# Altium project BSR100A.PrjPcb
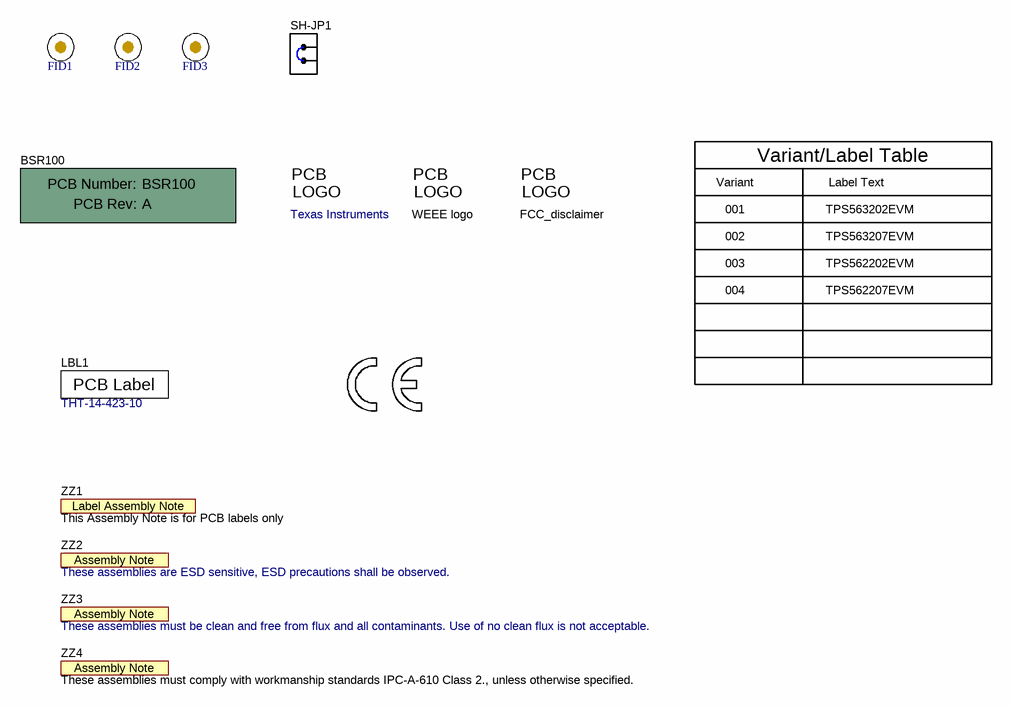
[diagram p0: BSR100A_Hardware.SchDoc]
CopyrightYear: 2019; PCB_Layout: Zhao Ma; PCB_Rev: A; PRJ_Customer: Public Release; PRJ_Engineer: Zhao Ma; PRJ_Number: BSR100; PRJ_Title: BSR100; SCH_Rev: A; TechSupport: http://www.ti.com/support; TID: A0223841
2 sheets, 47 parts. Net scope: global (net labels, ports and power ports of the same name join across sheets).
Board file: BSR100A.PcbDoc
Sheets:
  BSR100A_Hardware.SchDoc
  BSR100A.SchDoc

## Sheet BSR100A_Hardware.SchDoc
size 431 x 279 mm; Date: Not shown in title block; ApprovedBy: Not shown in title block; CheckedBy: Not shown in title block; Author: Not shown in title block; CompanyName: Not shown in title block; Engineer: Not shown in title block; Organization: Not shown in title block; Address1: Not shown in title block; Address2: Not shown in title block; Address3: Not shown in title block; Address4: Not shown in title block; DocumentNumber: 1; Revision: Use project parameter SCH_Rev; SheetNumber: 1; SheetTotal: 2; PageSetup: Record=PageOptions¦CenterHorizontal=True¦CenterVertical=True¦PrintScale=1.00¦XCorrection=1.00¦YCorrection=1.00¦PrintKind=0¦BorderSize=5000000¦LeftOffset=0¦BottomOffset=0¦Orientation=2¦PaperLength=1000¦PaperWidth=1000¦Scale=100¦PaperSource=15¦PrintQuality=600¦MediaType=1¦DitherType=10¦PaperKind=Letter¦PrintScaleMode=1

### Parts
!PCB1  PartNumber: BSR100  (hidden comment: Printed Circuit Board)  (mechanical)
FID1  Fiducial  [Fiducial10-20]  (value not drawn)
FID2  Fiducial  [Fiducial10-20]  (value not drawn)
FID3  Fiducial  [Fiducial10-20]  (value not drawn)
LBL1  THT-14-423-10  [Label_650x200]
Logo1  Texas Instruments  [TI_Stacked_Overlay_Small]  (no BOM)
Logo2  WEEE logo  [WEEE_Minimum]  (no BOM)
Logo3  FCC disclaimer  [FCC_disclaimer]  (value not drawn)  (no BOM)
LOGO4  CE Mark  [CE_Mark_5mm]  (value not drawn)  (no BOM)
SH-JP1  SNT-100-BK-G  [SNT-100-BK-G]  (value not drawn)
ZZ1  This Assembly Note is for PCB labels only  [AssemblyNoteLabel]  (no BOM)
ZZ2  These assemblies are ESD sensitive, ESD precautions shall be observed.  [AssemblyNote]  (no BOM)
ZZ3  These assemblies must be clean and free from flux and all contaminants. Use of no clean flux is not acceptable.  [AssemblyNote]  (no BOM)
ZZ4  These assemblies must comply with workmanship standards IPC-A-610 Class 2., unless otherwise specified.  [AssemblyNote]  (no BOM)

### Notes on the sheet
- Variant
- 001
- Variant/Label Table
- Label Text
- TPS563202EVM
- 002
- 003
- TPS563207EVM
- TPS562202EVM
- 004
- TPS562207EVM

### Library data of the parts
!PCB1 = CMP-0003618-2: Manufacturer: Any
FID1-FID3 = CMP-0077181-1: Fiducial mark.  There is nothing to buy or mount.
LBL1 = CMP-0003625-1: Thermal Transfer Printable Labels, 0.650" W x 0.200" H - 10,000 per roll; Manufacturer: Brady; Note: Size: 0.65" x 0.20 "
Logo1 = CMP-0074838-1: Texas Instrument Corporate Signature; SymbolCreator: a0412235; Lib Reference: TI_Logo
Logo2 = CMP-0074769-1
Logo3 = CMP-0074847-1: FCC_disclaimer; Library Reference: Logo
LOGO4 = CMP-0074844-1: SymbolCreator: a0412235
SH-JP1 = CMP-0003623-3: Shunt, 100mil, Gold plated, Black; Alternate PartNumber: 969102-0000-DA; Manufacturer: Samtec; Alternate Manufacturer: 3M; Value: 1x2; Note: You can "mate" this to a header by matching the designator.  i.e. use SH-J3 for header J3
ZZ1 = CMP-0003616-3
ZZ2 = CMP-0077236-1
ZZ3 = CMP-0077237-1
ZZ4 = AssemblyNote: SymbolCreator: codlsc

## Sheet BSR100A.SchDoc
size 431 x 279 mm; Date: Not shown in title block; ApprovedBy: Not shown in title block; CheckedBy: Not shown in title block; Author: Not shown in title block; CompanyName: Not shown in title block; Engineer: Not shown in title block; Organization: Not shown in title block; Address1: Not shown in title block; Address2: Not shown in title block; Address3: Not shown in title block; Address4: Not shown in title block; DocumentNumber: 1; Revision: Use project parameter SCH_Rev; SheetNumber: 2; SheetTotal: 3; PageSetup: Record=PageOptions¦CenterHorizontal=True¦CenterVertical=True¦PrintScale=1.00¦XCorrection=1.00¦YCorrection=1.00¦PrintKind=0¦BorderSize=5000000¦LeftOffset=0¦BottomOffset=0¦Orientation=2¦PaperLength=1000¦PaperWidth=1000¦Scale=100¦PaperSource=15¦PrintQuality=600¦MediaType=1¦DitherType=10¦PaperKind=Letter¦PrintScaleMode=1
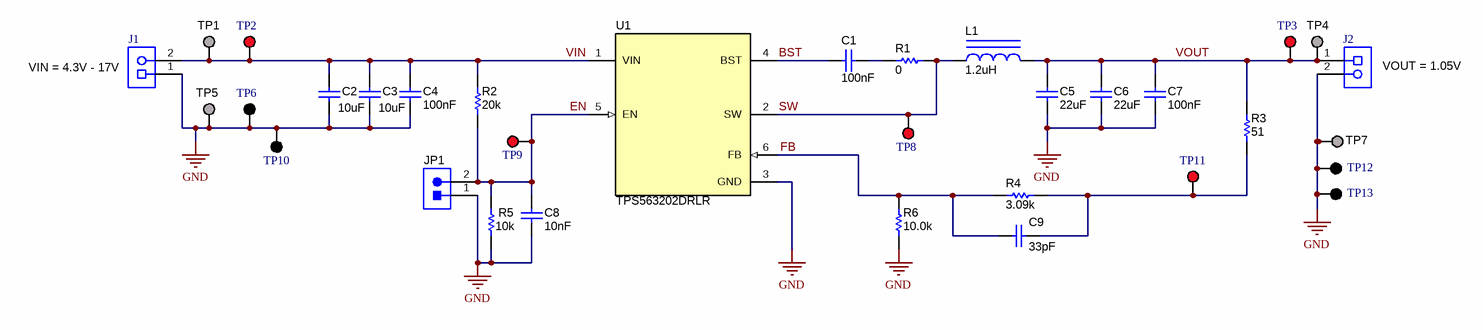
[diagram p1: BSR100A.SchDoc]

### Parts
C1  Cap_F: 100nF  [0603]  (hidden comment: C1608X7R1E104K080AA)
C2  ValueDisplayed: 10uF  [0805_HV]  (hidden comment: GRM21BR61E106MA73L)
C3  ValueDisplayed: 10uF  [0805_HV]  (hidden comment: GRM21BR61E106MA73L)
C4  Cap_F: 100nF  [0603]  (hidden comment: C1608X7R1E104K080AA)
C5  ValueDisplayed: 22uF  [0805_HV]  (hidden comment: GRM21BR61A226ME44L)
C6  ValueDisplayed: 22uF  [0805_HV]  (hidden comment: GRM21BR61A226ME44L)
C7  Cap_F: 100nF  [0603]  (hidden comment: C1608X7R1E104K080AA)
C8  Cap_F: 10nF  [0603]  (hidden comment: C1608X7R1H103K080AA)
C9  ValueDisplayed: 33pF  [0603]  (hidden comment: GRM1885C2A330JA01D)
J1  ED120/2DS  [On-Shore_ED120_2DS]  (value not drawn)
J2  ED120/2DS  [On-Shore_ED120_2DS]  (value not drawn)
JP1  PEC02SAAN  [CONN_PEC02SAAN]  (value not drawn)
L1  ValueDisplayed: 1.2uH  [WE-LHMI_7050]  (hidden comment: 74437349012)
R1  ValueDisplayed: 0  [0603]  (hidden comment: CRCW06030000Z0EA)
R2  ValueDisplayed: 20k  [0603]  (hidden comment: CRCW060320K0JNEA)
R3  ValueDisplayed: 51  [0603]  (hidden comment: CRCW060351R0JNEA)
R4  ValueDisplayed: 3.09k  [0603]  (hidden comment: RC0603FR-073K09L)
R5  ValueDisplayed: 10k  [0603]  (hidden comment: CRCW060310K0JNEA)
R6  value 10.0k  [0603]  (hidden comment: CRCW060310K0FKEA)
TP1  1502-2  [Keystone1502-2]  (value not drawn)
TP2  5000  [Keystone5000]  (value not drawn)
TP3  5000  [Keystone5000]  (value not drawn)
TP4  1502-2  [Keystone1502-2]  (value not drawn)
TP5  1502-2  [Keystone1502-2]  (value not drawn)
TP6  5001  [Keystone5001]  (value not drawn)
TP7  1502-2  [Keystone1502-2]  (value not drawn)
TP8  5000  [Keystone5000]  (value not drawn)
TP9  5000  [Keystone5000]  (value not drawn)
TP10  5001  [Keystone5001]  (value not drawn)
TP11  5000  [Keystone5000]  (value not drawn)
TP12  5001  [Keystone5001]  (value not drawn)
TP13  5001  [Keystone5001]  (value not drawn)
U1  TPS563202DRLR  [DRL0006A]

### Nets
GND: C2.2 C3.2 C4.2 C5.1 C6.1 C7.2 C8.2 J1.1 J2.2 JP1.1 R5.1 R6.1 TP5.1 TP6.1 TP7.1 TP10.1 TP12.1 TP13.1 U1.3(GND)
BST: C1.1 U1.4(BST)
EN: C8.1 JP1.2 R2.1 R5.2 TP9.1 U1.5(EN)
FB: C9.2 R4.2 R6.2 U1.6(FB)
SW: L1.1 R1.2 TP8.1 U1.2(SW)
VIN: C2.1 C3.1 C4.1 J1.2 R2.2 TP1.1 TP2.1 U1.1(VIN)
VOUT: C5.2 C6.2 C7.1 J2.1 L1.2 R3.2 TP3.1 TP4.1
NetC1_2: C1.2 R1.1
NetC9_1: C9.1 R3.1 R4.1 TP11.1

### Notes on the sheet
- (near J1) VIN = 4.3V - 17V
- (near J2) VOUT = 1.05V

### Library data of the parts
C1 C4 C7 = CMP-0007039-5: CAP, CERM, 0.1 uF, 25 V, +/- 10%, X7R, 0603; Manufacturer: TDK; TaMin_C: -55°C; Polarized: N; SizeAreaWB_mm2: 4.68; Value1: Unknown; U/M: EA; Value: 0.1uF; TaMax_C: 125°C; SizeZ_mm: 1; SizeX_mm: 1.6; SizeY_mm: 0.8; Value2: 25V; SizeArea_mm2: 1.28; AEC Category: Q200
C2 C3 = CMP-0008303-3: CAP, CERM, 10 uF, 25 V, +/- 20%, X5R, 0805; Manufacturer: MuRata; SizeZ_mm: 1.45; U/M: EA; SizeAreaWB_mm2: 6.75; Value2: 25V; TaMin_C: -55°C; Value1: Unknown; Cap_F: 10µF; SizeX_mm: 2; Cap_Case: 0805; TaMax_C: 85°C; Polarized: N; SizeY_mm: 1.25; AEC Category: Q200; SizeArea_mm2: 2.5; Value: 10uF
C5 C6 = CMP-0008286-2: CAP, CERM, 22 uF, 10 V, +/- 20%, X5R, 0805; Manufacturer: MuRata; Polarized: N; Value: 22uF; U/M: EA; Cap_F: 22µF; Value1: Unknown; VDC_V: 10V; TaMin_C: -55°C; TaMax_C: 85°C; Cap_Case: 0805; SizeArea_mm2: 2.5; SizeAreaWB_mm2: 6.75; SizeX_mm: 2; SizeY_mm: 1.25; SizeZ_mm: 1.45; AEC Category: Q200
C8 = CMP-0007043-4: CAP, CERM, 0.01 uF, 50 V, +/- 10%, X7R, 0603; Manufacturer: TDK; TaMin_C: -55°C; ESR_ohm: 0.0539; Polarized: N; SizeAreaWB_mm2: 4.68; Value1: 0.0539 ohm; U/M: EA; Value: 0.01uF; TaMax_C: 125°C; SizeZ_mm: 1; SizeX_mm: 1.6; SizeY_mm: 0.8; Value2: 50V; SizeArea_mm2: 1.28; AEC Category: Q200
C9 = CMP-0007263-4: CAP, CERM, 33 pF, 100 V, +/- 5%, C0G/NP0, 0603; Manufacturer: MuRata; TaMin_C: -55°C; Polarized: N; SizeAreaWB_mm2: 4.68; Value1: Unknown; U/M: EA; Value: 33pF; TaMax_C: 125°C; SizeZ_mm: 1; SizeX_mm: 1.6; SizeY_mm: 0.8; Value2: 100V; SizeArea_mm2: 1.28; AEC Category: Q200
J1 J2 = CMP-0074910-1: Terminal Block, 5.08 mm, 2x1, Brass, TH; Manufacturer: On-Shore Technology; Pitch_mm: 5.08; Gender: Female; Shrouded: N; Row_Count: 1; Current_A: 15A; Voltage_V: 300V; Cert_CULUS: Y; CNHeader: False; CT: True; Green_Lifecycle: Not Set; Green_REACh: Incomplete
JP1 = CMP-0002337-1: Header, 100mil, 2x1, Tin, TH; Manufacturer: Sullins Connector Solutions; Pitch_mm: 2.54; Gender: Male; Shrouded: N; Row_Count: 1; Current_A: 3A; Voltage_V: 1.8kV; Cert_UL: Y; CNHeader: TRUE; CT: FALSE; Green_Lifecycle: Not Set; Green_REACh: Incomplete
L1 = CMP-0064104-1: Inductor, Shielded Drum Core, Powdered Iron, 1.2 uH, 9 A, 0.0072 ohm, SMD; Manufacturer: Wurth Elektronik; Isat: 18A @ 20% inductance drop; Irms: 9A @ 40C rise; Green_Lifecycle: Active; SizeAreaWB_mm2: 73.96; DCR_ohm: 7.2m; Green_REACh: Passed; Value: 1.2uH; Imax_A: 9A; SizeZ_mm: 5; SizeX_mm: 6.6; SizeArea_mm2: 43.56; Ind_H: 1.2µH; AEC Category: Q200
R1 = CMP-0025697-4: RES, 0, 5%, 0.1 W, AEC-Q200 Grade 0, 0603; Manufacturer: Vishay-Dale; Power_W: 100mW; TempCo: 200 ppm/C; Value_Code: 0000; Value: 0; EIA_Code: E24; SizeX_mm: 1.6; SizeY_mm: 0.8; SizeZ_mm: 1; Value2: 0.1W; SizeArea_mm2: 1.28; AEC Qualified: Y; VDC_V: 75V; AEC Category: Q200
R2 = CMP-0025753-4: RES, 20 k, 5%, 0.1 W, AEC-Q200 Grade 0, 0603; Manufacturer: Vishay-Dale; Value: 20k; Value_Code: 20k0; Power_W: 100mW; Value2: 0.1W; VDC_V: 75V; TempCo: 200 ppm/C; EIA_Code: E24; SizeArea_mm2: 1.28; SizeX_mm: 1.6; SizeY_mm: 0.8; SizeZ_mm: 1; AEC Category: Q200; AEC Qualified: Y; AEC Grade: 0
R3 = CMP-0025825-4: RES, 51, 5%, 0.1 W, AEC-Q200 Grade 0, 0603; Manufacturer: Vishay-Dale; Value: 51; Value_Code: 51R0; Power_W: 100mW; Value2: 0.1W; VDC_V: 75V; TempCo: 200 ppm/C; EIA_Code: E24; SizeArea_mm2: 1.28; SizeX_mm: 1.6; SizeY_mm: 0.8; SizeZ_mm: 1; AEC Category: Q200; AEC Qualified: Y; AEC Grade: 0
R4 = CMP-0023077-5: RES, 3.09 k, 1%, 0.1 W, 0603; Manufacturer: Yageo; Power_W: 100mW; TempCo: 100 ppm/C; Value_Code: 3k09; Value: 3.09k; EIA_Code: E96; SizeX_mm: 1.6; SizeY_mm: 0.8; SizeZ_mm: 1; Value2: 0.1W; SizeArea_mm2: 1.28; AEC Qualified: N; VDC_V: 75V; AEC Category: Q200; SizeAreaWB_mm2: 4.68
R5 = CMP-0025701-4: RES, 10 k, 5%, 0.1 W, AEC-Q200 Grade 0, 0603; Manufacturer: Vishay-Dale; Value: 10k; Value_Code: 10k0; Power_W: 100mW; Value2: 0.1W; VDC_V: 75V; TempCo: 200 ppm/C; EIA_Code: E24; SizeArea_mm2: 1.28; SizeX_mm: 1.6; SizeY_mm: 0.8; SizeZ_mm: 1; AEC Category: Q200; AEC Qualified: Y; AEC Grade: 0
R6 = CMP-0021998-4: RES, 10.0 k, 1%, 0.1 W, AEC-Q200 Grade 0, 0603; Manufacturer: Vishay-Dale; Res_ohm: 10k; Value_Code: 10k0; Power_W: 100mW; Value2: 0.1W; VDC_V: 75V; TempCo: 100 ppm/C; EIA_Code: E96; AEC Category: Q200; AEC Grade: 0; AEC Qualified: Y; SizeArea_mm2: 1.28; SizeX_mm: 1.6; SizeY_mm: 0.8; SizeZ_mm: 1
TP1 TP4 TP5 TP7 = CMP-0055113-1: Terminal, Turret, TH, Double; Manufacturer: Keystone; CompType: Turret Terminal; CNHeader: FALSE; Green_Lifecycle: Active; Green_REACh: Passed
TP2 TP3 TP8 TP9 TP11 = CMP-0055137-1: Test Point, Miniature, Red, TH; Manufacturer: Keystone; ContactFinish: Silver; Green_Lifecycle: Active; Green_REACh: Passed; CNHeader: FALSE; CT: TRUE
TP6 TP10 TP12 TP13 = CMP-0055138-1: Test Point, Miniature, Black, TH; Manufacturer: Keystone; ContactFinish: Silver; Green_Lifecycle: Active; Green_REACh: Passed; CNHeader: FALSE; CT: TRUE
U1 = CMP-0860517-1: 4.5-V to 17-V Input, 3-A Synchronous Buck Converter, DRL0006A (SOT-5X3-6); Manufacturer: Texas Instruments; Alternate PartNumber: TPS563202DRLT; SizeX_mm: 1.6; AEC Category: Q200; SizeZ_mm: 0.6; CompType: IC; AEC Qualified: N; SizeAreaWB_mm2: 6.76; SizeArea_mm2: 2.56

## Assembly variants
001: not fitted C8 C9 FID1 FID2 FID3 R5; alternate parts L1 -> CMP-0064104-1, U1 -> CMP-0860517-1
002: not fitted C8 C9 FID1 FID2 FID3 R5; alternate parts L1 -> CMP-0064104-1, U1 -> CMP-0860979-1
003: not fitted C8 C9 FID1 FID2 FID3 R5; alternate parts L1 -> CMP-0064106-1, U1 -> CMP-0860978-1
004: not fitted C8 C9 FID1 FID2 FID3 R5; alternate parts L1 -> CMP-0064106-1, U1 -> CMP-0860516-1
